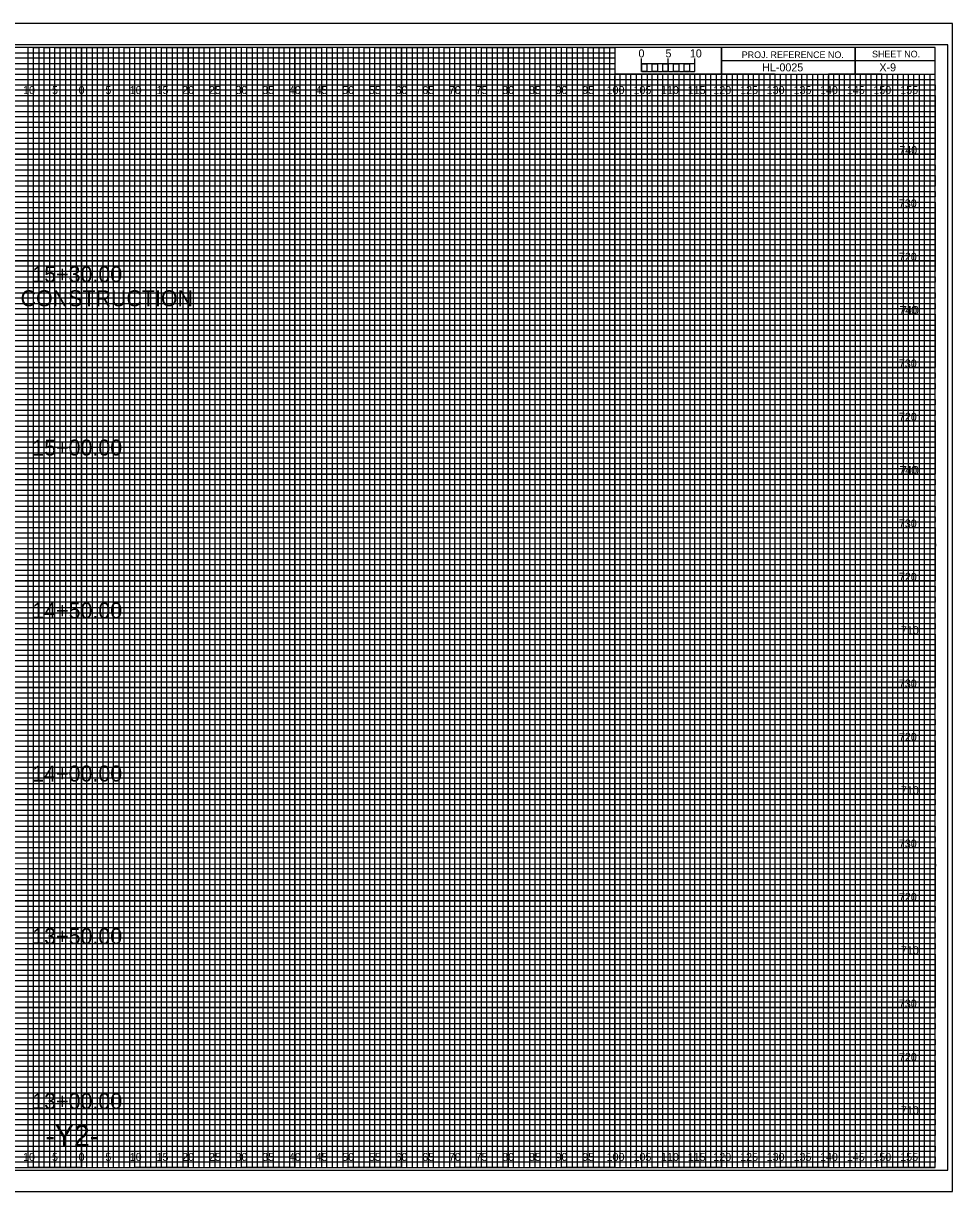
# Model space of a CAD drawing. Extents: x -13 to 323, y -5 to 654.
# Drawn here: x 149.1 to 323.3, y 215.5 to 434.5 of the extents above; entities that cross this region are included whole.
import ezdxf

# ---------------------------------------------------------------- set-up
doc = ezdxf.new("R2010")
doc.units = 0
for name, color, linetype in [('Exist CMT Pavement', 7, 'Continuous'), ('Exist Cross Section Cell', 7, 'Continuous'), ('Exist XS Center Line Elevation Label', 7, 'Continuous'), ('Exist XS Ground Line', 7, 'Continuous'), ('Prop CMT Pvmt Course 1', 7, 'Continuous'), ('Prop CMT Pvmt Course 1 Wedge', 7, 'Continuous'), ('Prop CMT Pvmt Course 2', 7, 'Continuous'), ('Prop CMT Pvmt Course 3', 7, 'Continuous'), ('Prop CMT Pvmt Surface', 7, 'Continuous'), ('Prop CMT Pvmt Surface Shoulder', 7, 'Continuous'), ('Prop CMT Pvmt Wedge Surface 1', 7, 'Continuous'), ('Prop CMT Shld Paved Course 1', 7, 'Continuous'), ('Prop CMT Shld Paved Course 2', 7, 'Continuous'), ('Prop CMT Shld Paved Course 3', 7, 'Continuous'), ('Prop CMT Slope Grass', 7, 'Continuous'), ('Prop CMT Subgrade Earthwork', 7, 'Continuous'), ('Scratch_Level_1', 7, 'Continuous')]:
    doc.layers.add(name, color=color, linetype=linetype)

msp = doc.modelspace()

# ---------------------------------------------------------------- linework, layer by layer
at = {"layer": 'Exist XS Center Line Elevation Label'}
for points in [[(145, 220), (155, 220), (155, 430), (165, 430), (165, 220), (175, 220), (175, 430), (185, 430), (185, 220), (195, 220), (195, 430), (205, 430), (205, 220), (215, 220), (215, 430), (225, 430), (225, 220), (235, 220), (235, 430), (245, 430), (245, 220), (255, 220), (255, 430), (259.93, 430), (260, 430), (260, 425), (264.99, 425), (264.99, 220), (275, 220), (275, 425), (285, 425), (285, 220), (295, 220), (295, 425), (305, 425), (305, 220), (315, 220), (315, 425)], [(0, 425), (275, 425)], [(0, 405), (320, 405), (320, 415), (0, 415)], [(0, 385), (320, 385), (320, 395), (0, 395)], [(0, 365), (320, 365), (320, 375), (0, 375)], [(0, 345), (320, 345), (320, 355), (0, 355)], [(0, 325), (320, 325), (320, 335), (0, 335)], [(0, 305), (320, 305), (320, 315), (0, 315)], [(0, 285), (320, 285), (320, 295), (0, 295)], [(0, 265), (320, 265), (320, 275), (0, 275)], [(0, 245), (320, 245), (320, 255), (0, 255)], [(0, 225), (320, 225), (320, 235), (0, 235)]]:
    msp.add_lwpolyline(points, dxfattribs=at)
at = {"layer": 'Exist XS Ground Line'}
for p, q in [((150, 430), (140, 430)), ((150, 220), (150, 430)), ((170, 430), (160, 430)), ((160, 430), (160, 220)), ((170, 220), (170, 430)), ((190, 430), (180, 430)), ((180, 430), (180, 220)), ((190, 220), (190, 430)), ((210, 430), (200, 430)), ((200, 430), (200, 220)), ((210, 220), (210, 430)), ((230, 430), (220, 430)), ((220, 430), (220, 220)), ((230, 220), (230, 430)), ((250, 430), (240, 430)), ((240, 430), (240, 220)), ((250, 220), (250, 430)), ((260, 430), (260, 220)), ((270, 220), (270, 425)), ((290, 425), (280, 425)), ((280, 425), (280, 220)), ((290, 220), (290, 425)), ((310, 425), (300, 425)), ((300, 425), (300, 220)), ((310, 220), (310, 425)), ((160, 220), (150, 220)), ((180, 220), (170, 220)), ((200, 220), (190, 220)), ((220, 220), (210, 220)), ((240, 220), (230, 220)), ((260, 220), (250, 220)), ((280, 220), (270, 220)), ((300, 220), (290, 220)), ((320, 220), (310, 220)), ((320, 220), (320, 220))]:
    msp.add_line(p, q, dxfattribs=at)
for points in [[(0, 420), (320, 420), (320, 410), (0, 410)], [(0, 400), (320, 400), (320, 390), (0, 390)], [(0, 380), (320, 380), (320, 370), (0, 370)], [(0, 360), (320, 360), (320, 350), (0, 350)], [(0, 340), (320, 340), (320, 330), (0, 330)], [(0, 320), (320, 320), (320, 310), (0, 310)], [(0, 300), (320, 300), (320, 290), (0, 290)], [(0, 280), (320, 280), (320, 270), (0, 270)], [(0, 260), (320, 260), (320, 250), (0, 250)], [(0, 240), (320, 240), (320, 230), (0, 230)]]:
    msp.add_lwpolyline(points, dxfattribs=at)
at = {"layer": 'Prop CMT Pvmt Course 2'}
msp.add_lwpolyline([(-13.4, 215.5), (323.3, 215.5), (323.3, 434.5), (-13.4, 434.5)], close=True, dxfattribs=at)
at = {"layer": 'Prop CMT Pvmt Course 3'}
msp.add_lwpolyline([(-10.8, 219.5), (322.4, 219.5), (322.4, 430.5), (-10.8, 430.5)], close=True, dxfattribs=at)
msp.add_lwpolyline([(-10.8, 219.5), (322.4, 219.5), (322.4, 430.5), (-10.8, 430.5)], close=True, dxfattribs=at)
at = {"layer": 'Prop CMT Pvmt Surface'}
for p, q in [((323.3, 434.5), (-13.4, 434.5)), ((323.3, 434.5), (-13.4, 434.5)), ((-13.4, 215.5), (323.3, 215.5)), ((-13.4, 215.5), (323.3, 215.5))]:
    msp.add_line(p, q, dxfattribs=at)
at = {"layer": 'Prop CMT Shld Paved Course 1'}
for p, q in [((305, 430), (305, 425)), ((305, 425), (305, 430)), ((280, 427.5), (280, 425)), ((320, 427.49), (280, 427.49)), ((280, 425), (320, 425))]:
    msp.add_line(p, q, dxfattribs=at)
for points in [[(320, 430), (0, 430), (0, 220), (320, 220)], [(280, 430), (260, 430), (260, 425.03), (280, 425.03)], [(320, 430), (280, 430), (280, 425), (320, 425)]]:
    msp.add_lwpolyline(points, close=True, dxfattribs=at)
at = {"layer": 'Prop CMT Shld Paved Course 2'}
for p, q in [((267, 425), (266.01, 425)), ((266.01, 425), (266.01, 220)), ((267, 220), (267, 425)), ((269, 425), (268, 425)), ((268, 425), (268, 220)), ((269, 220), (269, 425)), ((266.01, 220), (265, 220)), ((268, 220), (267, 220))]:
    msp.add_line(p, q, dxfattribs=at)
for points in [[(150, 220), (151, 220), (151, 430), (152, 430), (152, 220)], [(152, 220), (153, 220), (153, 430), (154, 430), (154, 220)], [(155, 220), (156, 220), (156, 430), (157, 430), (157, 220)], [(157, 220), (158, 220), (158, 430), (159, 430), (159, 220)], [(160, 220), (161, 220), (161, 430), (162, 430), (162, 220)], [(162, 220), (163, 220), (163, 430), (164, 430), (164, 220)], [(165, 220), (166, 220), (166, 430), (167, 430), (167, 220)], [(167, 220), (168, 220), (168, 430), (169, 430), (169, 220)], [(170, 220), (171, 220), (171, 430), (172, 430), (172, 220)], [(172, 220), (173, 220), (173, 430), (174, 430), (174, 220)], [(175, 220), (176, 220), (176, 430), (177, 430), (177, 220)], [(177, 220), (178, 220), (178, 430), (179, 430), (179, 220)], [(180, 220), (181, 220), (181, 430), (182, 430), (182, 220)], [(182, 220), (183, 220), (183, 430), (184, 430), (184, 220)], [(185, 220), (186, 220), (186, 430), (187, 430), (187, 220)], [(187, 220), (188, 220), (188, 430), (189, 430), (189, 220)], [(190, 220), (191, 220), (191, 430), (192, 430), (192, 220)], [(192, 220), (193, 220), (193, 430), (194, 430), (194, 220)], [(195, 220), (196, 220), (196, 430), (197, 430), (197, 220)], [(197, 220), (198, 220), (198, 430), (199, 430), (199, 220)], [(200, 220), (201, 220), (201, 430), (202, 430), (202, 220)], [(202, 220), (203, 220), (203, 430), (204, 430), (204, 220)], [(205, 220), (206, 220), (206, 430), (207, 430), (207, 220)], [(207, 220), (208, 220), (208, 430), (209, 430), (209, 220)], [(210, 220), (211, 220), (211, 430), (212, 430), (212, 220)], [(212, 220), (213, 220), (213, 430), (214, 430), (214, 220)], [(215, 220), (216, 220), (216, 430), (217, 430), (217, 220)], [(217, 220), (218, 220), (218, 430), (219, 430), (219, 220)], [(220, 220), (221, 220), (221, 430), (222, 430), (222, 220)], [(222, 220), (223, 220), (223, 430), (224, 430), (224, 220)], [(225, 220), (226, 220), (226, 430), (227, 430), (227, 220)], [(227, 220), (228, 220), (228, 430), (229, 430), (229, 220)], [(230, 220), (231, 220), (231, 430), (232, 430), (232, 220)], [(232, 220), (233, 220), (233, 430), (234, 430), (234, 220)], [(235, 220), (236, 220), (236, 430), (237, 430), (237, 220)], [(237, 220), (238, 220), (238, 430), (239, 430), (239, 220)], [(240, 220), (241, 220), (241, 430), (242, 430), (242, 220)], [(242, 220), (243, 220), (243, 430), (244, 430), (244, 220)], [(245, 220), (246, 220), (246, 430), (247, 430), (247, 220)], [(247, 220), (248, 220), (248, 430), (249, 430), (249, 220)], [(250, 220), (251, 220), (251, 430), (252, 430), (252, 220)], [(252, 220), (253, 220), (253, 430), (254, 430), (254, 220)], [(255, 220), (256, 220), (256, 430), (257, 430), (257, 220)], [(257, 220), (258, 220), (258, 430), (259, 430), (259, 220)], [(260, 220), (261, 220), (261, 425), (262.02, 425), (262.02, 220)], [(262, 220), (263, 220), (263, 425), (263.99, 425), (263.99, 220)], [(270, 220), (270.98, 220), (270.98, 425), (272, 425), (272, 220)], [(272, 220), (273, 220), (273, 425), (274.05, 425), (274.05, 220)], [(275, 220), (276, 220), (276, 425), (277, 425), (277, 220)], [(277, 220), (278, 220), (278, 425), (279, 425), (279, 220)], [(280, 220), (281, 220), (281, 425), (282, 425), (282, 220)], [(282, 220), (283, 220), (283, 425), (284, 425), (284, 220)], [(285, 220), (286, 220), (286, 425), (287, 425), (287, 220)], [(287, 220), (288, 220), (288, 425), (289, 425), (289, 220)], [(290, 220), (291, 220), (291, 425), (292, 425), (292, 220)], [(292, 220), (293, 220), (293, 425), (294, 425), (294, 220)], [(295, 220), (296, 220), (296, 425), (297, 425), (297, 220)], [(297, 220), (298, 220), (298, 425), (299, 425), (299, 220)], [(300, 220), (301, 220), (301, 425), (302, 425), (302, 220)], [(302, 220), (303, 220), (303, 425), (304, 425), (304, 220)], [(305, 220), (306, 220), (306, 425), (307, 425), (307, 220)], [(307, 220), (308, 220), (308, 425), (309, 425), (309, 220)], [(310, 220), (311, 220), (311, 425), (312, 425), (312, 220)], [(312, 220), (313, 220), (313, 425), (314, 425), (314, 220)], [(315, 220), (316, 220), (316, 425), (317, 425), (317, 220)], [(317, 220), (318, 220), (318, 425), (319, 425), (319, 220)]]:
    msp.add_lwpolyline(points, dxfattribs=at)
at = {"layer": 'Prop CMT Shld Paved Course 3'}
for p, q in [((265, 425.49), (265, 427.9)), ((265, 426.9), (265, 427.9)), ((270, 425.49), (270, 427.9)), ((275, 425.49), (275, 427.9)), ((275, 426.9), (275, 427.9))]:
    msp.add_line(p, q, dxfattribs=at)
for points in [[(275, 426.9), (265, 426.9), (265, 425.49), (275, 425.49)], [(265, 426.9), (266, 426.9), (266, 425.49), (265, 425.49)], [(267, 426.9), (268, 426.9), (268, 425.49), (267, 425.49)], [(269, 426.9), (270, 426.9), (270, 425.49), (269, 425.49)], [(271, 426.9), (272, 426.9), (272, 425.49), (271, 425.49)], [(273, 426.9), (274, 426.9), (274, 425.49), (273, 425.49)]]:
    msp.add_lwpolyline(points, close=True, dxfattribs=at)
at = {"layer": 'Prop CMT Subgrade Earthwork'}
for p, q in [((150, 220), (150, 430)), ((150, 220), (150, 430)), ((160, 220), (160, 430)), ((160, 220), (160, 430)), ((170, 220), (170, 430)), ((170, 220), (170, 430)), ((180, 220), (180, 430)), ((180, 220), (180, 430)), ((190, 220), (190, 430)), ((190, 220), (190, 430)), ((200, 220), (200, 430)), ((200, 220), (200, 430)), ((210, 220), (210, 430)), ((210, 220), (210, 430)), ((220, 220), (220, 430)), ((220, 220), (220, 430)), ((230, 220), (230, 430)), ((230, 220), (230, 430)), ((240, 220), (240, 430)), ((240, 220), (240, 430)), ((250, 220), (250, 430)), ((250, 220), (250, 430)), ((260, 220), (260, 424.69)), ((260, 220), (260, 424.69)), ((270, 220), (270, 424.69)), ((270, 220), (270, 424.69)), ((280, 220), (280, 424.69)), ((280, 220), (280, 424.69)), ((290, 220), (290, 424.69)), ((290, 220), (290, 424.69)), ((300, 220), (300, 424.69)), ((300, 220), (300, 424.69)), ((310, 220), (310, 424.69)), ((310, 220), (310, 424.69)), ((0, 420), (320, 420)), ((0, 420), (320, 420)), ((0, 410), (320, 410)), ((0, 410), (320, 410)), ((0, 400), (320, 400)), ((0, 400), (320, 400)), ((0, 390), (320, 390)), ((0, 390), (320, 390)), ((0, 380), (320, 380)), ((0, 380), (320, 380)), ((0, 370), (320, 370)), ((0, 370), (320, 370)), ((0, 360), (320, 360)), ((0, 360), (320, 360)), ((0, 350), (320, 350)), ((0, 350), (320, 350)), ((0, 340), (320, 340)), ((0, 340), (320, 340)), ((0, 330), (320, 330)), ((0, 330), (320, 330)), ((0, 320), (320, 320)), ((0, 320), (320, 320)), ((0, 310), (320, 310)), ((0, 310), (320, 310)), ((0, 300), (320, 300)), ((0, 300), (320, 300)), ((0, 290), (320, 290)), ((0, 290), (320, 290)), ((0, 280), (320, 280)), ((0, 280), (320, 280)), ((0, 270), (320, 270)), ((0, 270), (320, 270)), ((0, 260), (320, 260)), ((0, 260), (320, 260)), ((0, 250), (320, 250)), ((0, 250), (320, 250)), ((0, 240), (320, 240)), ((0, 240), (320, 240)), ((0, 230), (320, 230)), ((0, 230), (320, 230))]:
    msp.add_line(p, q, dxfattribs=at)
at = {"layer": 'Scratch_Level_1'}
for p, q in [((0, 429), (260, 429)), ((260, 427.98), (0, 427.98)), ((260, 429), (260, 427.98)), ((0, 427), (260, 427)), ((260, 425.89), (0, 425.89)), ((260, 427), (260, 425.89)), ((0, 424), (320, 424))]:
    msp.add_line(p, q, dxfattribs=at)
for points in [[(0, 423), (270, 423), (320, 423), (320, 422), (0, 422)], [(0, 421), (320, 421), (320, 419), (0, 419)], [(0, 418), (320, 418), (320, 417), (0, 416.98)], [(0, 416), (320, 416), (320, 414), (0, 414)], [(0, 413), (320, 413), (320, 412), (0, 412)], [(0, 411), (320, 411), (320, 409), (0, 409)], [(0, 408), (320, 408), (320, 407), (0, 407)], [(0, 406), (320, 406), (320, 404), (0, 404)], [(0, 403), (320, 403), (320, 402), (0, 402)], [(0, 401), (320, 401), (320, 399), (0, 399)], [(0, 398), (320, 398), (320, 397), (0, 397)], [(0, 396), (320, 396), (320, 393.95), (320, 393), (320, 392), (0, 392)], [(0, 394), (320, 394), (320, 393), (0, 393)], [(0, 391), (320, 391), (320, 389), (0, 389.03)], [(0, 389.03), (320, 389), (320, 388), (0, 388)], [(0, 387), (320, 387), (320, 386), (0, 386)], [(0, 384), (320, 384), (320, 383), (0, 383)], [(0, 382), (320, 382), (320, 381), (0, 381)], [(-0.07, 378.89), (320, 378.89), (320, 377.88), (-0.07, 377.88)], [(0, 377), (320, 377), (320, 376), (0, 376)], [(0, 374), (320, 374), (320, 373), (0, 373)], [(0, 372), (320, 372), (320, 371), (0, 371)], [(0, 369), (320, 369), (320, 368), (0, 368)], [(0, 367), (320, 367), (320, 366), (0, 366)], [(0, 364), (320, 364), (320, 363), (0, 363)], [(0, 362), (320, 362), (320, 361), (0, 361)], [(0, 359), (320, 359), (319.99, 357.98), (0, 358)], [(0, 357), (320, 357), (320, 356), (0, 356)], [(0, 354), (320, 354), (320, 353), (0, 353)], [(0, 352), (320, 352), (320, 351), (0, 351)], [(0, 349), (320, 349), (320, 348), (0, 348)], [(0, 347), (320, 347), (320, 346), (0, 346)], [(0, 344), (320, 344), (320, 343), (0, 343)], [(0, 342), (320, 342), (320, 341), (0, 341)], [(0, 339), (320, 339), (320, 338), (0, 338)], [(0, 336.99), (320.07, 336.91), (320, 336), (0, 336)], [(0, 334), (320, 334), (320, 333), (0, 333)], [(0, 332), (320, 332), (320, 331), (0, 331)], [(0, 329), (320, 329), (320, 328), (0, 328)], [(0, 327), (320, 327), (320, 326), (0, 326)], [(0, 324), (320, 324), (320, 323), (0, 323)], [(0, 322), (320, 322), (320, 321), (0, 321)], [(0, 319), (320, 319), (320, 318), (0, 318)], [(0, 317), (320, 317), (320, 316), (0, 316)], [(0, 314), (320, 314), (320, 313), (0, 313)], [(0, 312), (320, 312), (320, 311), (0, 311)], [(0, 309), (320, 309), (320, 308), (0, 308)], [(0, 307), (320, 307), (320, 306), (0, 306)], [(0, 304), (320, 304), (320, 303), (0, 303)], [(0, 302), (320, 302), (320, 301), (0, 301)], [(0, 299), (320, 299), (319.99, 297.98), (0, 298)], [(0, 297), (320, 297), (320, 296), (0, 296)], [(0, 294), (320, 294), (320, 293), (0, 293)], [(0, 292), (320, 292), (320, 291), (0, 291)], [(0, 289), (320, 289), (320, 288), (0, 288)], [(0, 287), (320, 287), (320, 286), (0, 286)], [(0, 284), (320, 284), (320, 283), (0, 283)], [(0, 282), (320, 282), (320, 281), (0, 281)], [(0, 279), (320, 279), (320, 278), (0, 278)], [(0, 276.99), (320.07, 276.91), (320, 276), (0, 276)], [(0, 274), (320, 274), (320, 273), (0, 273)], [(0, 272), (320, 272), (320, 271), (0, 271)], [(0, 269), (320, 269), (320, 268), (0, 268)], [(0, 267), (320, 267), (320, 266), (0, 266)], [(0, 264), (320, 264), (320, 263), (0, 263)], [(0, 262), (320, 262), (320, 261), (0, 261)], [(0, 259), (320, 259), (320, 258), (0, 258)], [(0, 257), (320, 257), (320, 256), (0, 256)], [(0, 254), (320, 254), (320, 253), (0, 253)], [(0, 252), (320, 252), (320, 251), (0, 251)], [(0, 249), (320, 249), (320, 248), (0, 248)], [(0, 247), (320, 247), (320, 246), (0, 246)], [(0, 244), (320, 244), (320, 243), (0, 243)], [(0, 242), (320, 242), (320, 241), (0, 241)], [(0, 239), (320, 239), (320, 238), (0, 238)], [(0, 237), (320, 237), (320, 236), (0, 236)], [(0, 234), (320, 234), (320, 233), (0, 233)], [(0, 232), (320, 232), (320, 231), (0, 231)], [(0, 229), (320, 229), (320, 228), (0, 228)], [(0, 227), (320, 227), (320, 226), (0, 226)], [(0, 224), (320, 224), (320, 223), (0, 223)], [(0, 222), (320, 222), (320, 221), (0, 221)]]:
    msp.add_lwpolyline(points, dxfattribs=at)

# ---------------------------------------------------------------- texts
at = {"layer": 'Exist CMT Pavement'}
msp.add_text('-Y2-', height=4, dxfattribs=at).set_placement((153.21, 224))
at = {"layer": 'Exist Cross Section Cell'}
for s, p in [('10', (149.04, 421.25)), ('5', (154.47, 421.25)), ('0', (159.45, 421.25)), ('0', (159.45, 421.25)), ('5', (164.47, 421.25)), ('10', (169.04, 421.25)), ('15', (174.06, 421.25)), ('20', (178.86, 421.25)), ('25', (183.88, 421.25)), ('30', (188.86, 421.25)), ('35', (193.88, 421.25)), ('40', (198.86, 421.25)), ('45', (203.88, 421.25)), ('50', (208.86, 421.25)), ('55', (213.88, 421.25)), ('60', (218.86, 421.25)), ('65', (223.88, 421.25)), ('70', (228.86, 421.25)), ('75', (233.88, 421.25)), ('80', (238.86, 421.25)), ('85', (243.88, 421.25)), ('90', (248.86, 421.25)), ('95', (253.88, 421.25)), ('100', (258.44, 421.25)), ('105', (263.47, 421.25)), ('110', (268.62, 421.25)), ('115', (273.65, 421.25)), ('120', (278.44, 421.25)), ('125', (283.47, 421.25)), ('130', (288.44, 421.25)), ('135', (293.47, 421.25)), ('140', (298.44, 421.25)), ('145', (303.47, 421.25)), ('150', (308.44, 421.25)), ('155', (313.47, 421.25)), ('10', (149.04, 221.25)), ('5', (154.47, 221.25)), ('0', (159.45, 221.25)), ('0', (159.45, 221.25)), ('5', (164.47, 221.25)), ('10', (169.04, 221.25)), ('15', (174.06, 221.25)), ('20', (178.86, 221.25)), ('25', (183.88, 221.25)), ('30', (188.86, 221.25)), ('35', (193.88, 221.25)), ('40', (198.86, 221.25)), ('45', (203.88, 221.25)), ('50', (208.86, 221.25)), ('55', (213.88, 221.25)), ('60', (218.86, 221.25)), ('65', (223.88, 221.25)), ('70', (228.86, 221.25)), ('75', (233.88, 221.25)), ('80', (238.86, 221.25)), ('85', (243.88, 221.25)), ('90', (248.86, 221.25)), ('95', (253.88, 221.25)), ('100', (258.44, 221.25)), ('105', (263.47, 221.25)), ('110', (268.62, 221.25)), ('115', (273.65, 221.25)), ('120', (278.44, 221.25)), ('125', (283.47, 221.25)), ('130', (288.44, 221.25)), ('135', (293.47, 221.25)), ('140', (298.44, 221.25)), ('145', (303.47, 221.25)), ('150', (308.44, 221.25)), ('155', (313.47, 221.25))]:
    msp.add_text(s, height=1.5, dxfattribs=at).set_placement(p)
at = {"layer": 'Prop CMT Pvmt Course 1'}
for s, p in [('15+30.00', (150.77, 385.97)), ('END CONSTRUCTION', (138.99, 381.47)), ('15+00.00', (150.77, 353.48)), ('14+50.00', (150.77, 322.94)), ('14+00.00', (150.77, 292.38)), ('13+50.00', (150.77, 261.89)), ('13+00.00', (150.77, 230.97))]:
    msp.add_text(s, height=3, dxfattribs=at).set_placement(p)
at = {"layer": 'Prop CMT Pvmt Course 1 Wedge'}
msp.add_text('HL-0025', height=1.5, dxfattribs=at).set_placement((287.6, 425.5))
at = {"layer": 'Prop CMT Pvmt Surface Shoulder'}
for s, p in [('740', (313.3, 410)), ('730', (313.22, 400)), ('720', (313.23, 390)), ('740', (313.3, 380)), ('710', (313.61, 380)), ('730', (313.22, 370)), ('720', (313.23, 360)), ('740', (313.3, 350)), ('710', (313.61, 350)), ('730', (313.22, 340)), ('720', (313.23, 330)), ('710', (313.61, 320)), ('730', (313.22, 310)), ('720', (313.23, 300)), ('710', (313.61, 290)), ('730', (313.22, 280)), ('720', (313.23, 270)), ('710', (313.61, 260)), ('730', (313.22, 250)), ('720', (313.23, 240)), ('710', (313.61, 230))]:
    msp.add_text(s, height=1.5, dxfattribs=at).set_placement(p)
at = {"layer": 'Prop CMT Pvmt Wedge Surface 1'}
for s, p in [('5', (269.47, 428.12)), ('10', (274.04, 428.12))]:
    msp.add_text(s, height=1.5, dxfattribs=at).set_placement(p)
at = {"layer": 'Prop CMT Shld Paved Course 1'}
for s, p in [('PROJ. REFERENCE NO.', (283.77, 427.99)), ('SHEET NO.', (308.19, 428.12))]:
    msp.add_text(s, height=1.25, dxfattribs=at).set_placement(p)
at = {"layer": 'Prop CMT Shld Paved Course 3'}
msp.add_text('0', height=1.5, dxfattribs=at).set_placement((264.41, 428.12))
at = {"layer": 'Prop CMT Slope Grass'}
msp.add_text('X-9', height=1.5, dxfattribs=at).set_placement((309.57, 425.5))

doc.saveas('drawing.dxf')
